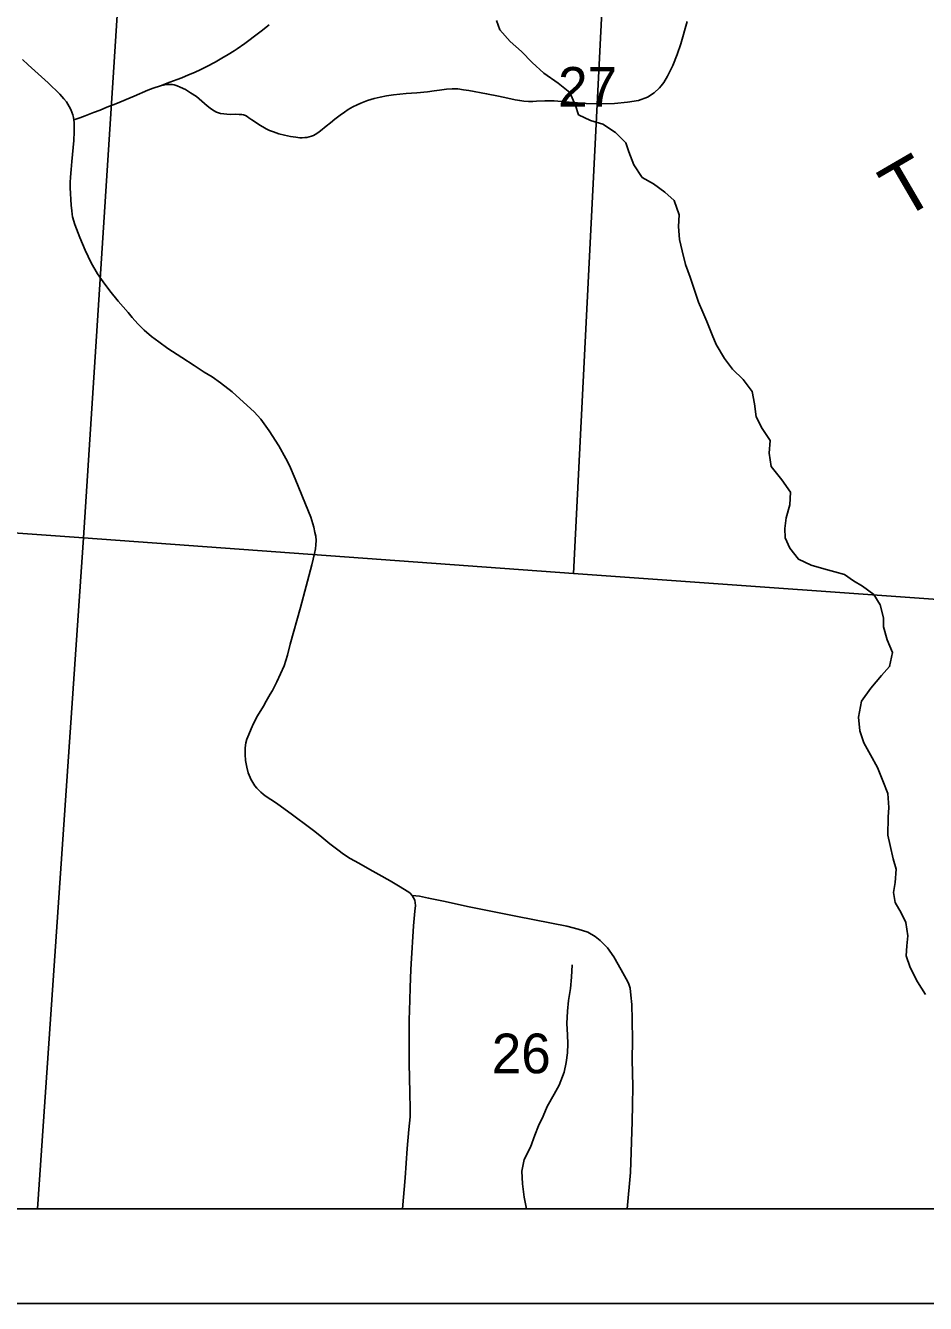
# Model space of a CAD drawing. Extents: x 0 to 34, y 0 to 22.
# Drawn here: x 4.184 to 5.134, y 14 to 15.349 of the extents above; entities that cross this region are included whole.
import ezdxf

# ---------------------------------------------------------------- set-up
doc = ezdxf.new("R2010")
doc.units = 0
for name, color, linetype in [('GM_X_Corporation', 7, 'Continuous'), ('GM_X_Minor_River', 7, 'Continuous'), ('GM_X_Section_Text', 7, 'Continuous'), ('GM_X_Township_Road', 7, 'Continuous'), ('GM_X_Township_Road_Text', 7, 'Continuous'), ('SH_Data', 7, 'Continuous')]:
    doc.layers.add(name, color=color, linetype=linetype)

msp = doc.modelspace()

# ---------------------------------------------------------------- linework, layer by layer
at = {"layer": 'GM_X_Corporation'}
for points in [[(3.3089, 15.8803), (3.31, 15.8916), (4.31, 15.819), (4.245, 14.8084), (3.2437, 14.8797)], [(4.31, 15.819), (4.8134, 15.7898), (4.7622, 14.7706), (4.245, 14.8084)], [(5.3151, 15.7607), (5.2401, 14.7366), (4.7622, 14.7706), (4.8134, 15.7898)], [(3.1916, 14.1), (4.1967, 14.1), (4.245, 14.8084), (3.2437, 14.8797)], [(4.1967, 14.1), (5.1981, 14.1), (5.2017, 14.1562), (5.23, 14.5792), (5.2401, 14.7366), (4.7622, 14.7706), (4.245, 14.8084)]]:
    msp.add_lwpolyline(points, close=True, dxfattribs=at)
at = {"layer": 'GM_X_Minor_River'}
for p, q in [((4.76, 14.3446), (4.7607, 14.3575)), ((4.759, 14.3324), (4.76, 14.3446)), ((4.7568, 14.3199), (4.759, 14.3324)), ((4.7558, 14.3085), (4.7568, 14.3199)), ((4.7551, 14.2956), (4.7558, 14.3085)), ((4.756, 14.2835), (4.7551, 14.2956)), ((4.7558, 14.2646), (4.7561, 14.274)), ((4.7561, 14.274), (4.756, 14.2835)), ((4.7544, 14.2543), (4.7558, 14.2646)), ((4.7522, 14.2441), (4.7544, 14.2543)), ((4.747, 14.2304), (4.7522, 14.2441)), ((4.7343, 14.2079), (4.7418, 14.2209)), ((4.7418, 14.2209), (4.747, 14.2304)), ((4.7303, 14.1976), (4.7343, 14.2079)), ((4.7254, 14.1874), (4.7303, 14.1976)), ((4.7214, 14.1775), (4.7254, 14.1874)), ((4.7169, 14.1649), (4.7214, 14.1775)), ((4.7077, 14.1398), (4.7102, 14.152)), ((4.7102, 14.152), (4.7169, 14.1649)), ((4.7082, 14.1262), (4.7077, 14.1398)), ((4.7102, 14.1122), (4.7082, 14.1262)), ((4.7122, 14.1016), (4.7102, 14.1122)), ((4.7122, 14.1), (4.7122, 14.1016))]:
    msp.add_line(p, q, dxfattribs=at)
for points in [[(5.0662, 14.6357), (5.0759, 14.6495), (5.0872, 14.6628), (5.0958, 14.6724), (5.0987, 14.6872), (5.0933, 14.7004), (5.0894, 14.7144), (5.0893, 14.7239), (5.0858, 14.7375), (5.0792, 14.7484), (5.067, 14.7574), (5.0575, 14.763), (5.048, 14.7697), (5.0378, 14.7723), (5.0264, 14.7756), (5.0128, 14.7793), (4.9995, 14.7856), (4.9903, 14.7972), (4.9856, 14.8082), (4.9852, 14.818), (4.9866, 14.8294), (4.9906, 14.8431), (4.9913, 14.8564), (4.9821, 14.8695), (4.9706, 14.8835), (4.9686, 14.8975), (4.9696, 14.9111), (4.9612, 14.9235), (4.955, 14.936), (4.953, 14.9496), (4.9506, 14.9629), (4.9411, 14.9753), (4.93, 14.9862), (4.9216, 14.9975), (4.9127, 15.0125), (4.9085, 15.0227), (4.9027, 15.0367), (4.8988, 15.0465), (4.8942, 15.0571), (4.8891, 15.0718), (4.8852, 15.0835), (4.8802, 15.0967), (4.8767, 15.1111), (4.8739, 15.1232), (4.8731, 15.1369), (4.8737, 15.1494), (4.8683, 15.1645), (4.8587, 15.1731), (4.8466, 15.1821), (4.8348, 15.1888), (4.8259, 15.202), (4.8205, 15.2156), (4.8174, 15.2254), (4.8064, 15.2363), (4.793, 15.2449), (4.7801, 15.2489), (4.7676, 15.2549), (4.7641, 15.2647), (4.7583, 15.2783), (4.7461, 15.2884), (4.7309, 15.2989), (4.7187, 15.3101), (4.7072, 15.3218), (4.6954, 15.3323), (4.6843, 15.3447), (4.6808, 15.3545)], [(5.1336, 14.326), (5.1252, 14.3395), (5.1175, 14.3546), (5.1132, 14.3671), (5.1139, 14.3777), (5.1149, 14.388), (5.1129, 14.4023), (5.1079, 14.4122), (5.1017, 14.4231), (5.0998, 14.4337), (5.1016, 14.4443), (5.1026, 14.4583), (5.0994, 14.4693), (5.0963, 14.4833), (5.0939, 14.4943), (5.0941, 14.5132), (5.0948, 14.5234), (5.0939, 14.5382), (5.0885, 14.5518), (5.0831, 14.5658), (5.0754, 14.579), (5.0685, 14.5918), (5.0642, 14.6046), (5.063, 14.619), (5.0662, 14.6357)]]:
    msp.add_lwpolyline(points, dxfattribs=at)
at = {"layer": 'GM_X_Township_Road'}
for points in [[(4.8545, 15.2853), (4.8576, 15.2891), (4.8615, 15.2956), (4.8671, 15.3068), (4.8716, 15.3184), (4.8755, 15.3298), (4.8821, 15.3532)], [(4.3265, 15.2856), (4.3363, 15.2892), (4.3438, 15.2921), (4.3487, 15.294), (4.3526, 15.2956), (4.3578, 15.2977), (4.3621, 15.2996), (4.369, 15.3028), (4.3753, 15.3059), (4.384, 15.3105), (4.3911, 15.3145), (4.3977, 15.3185), (4.404, 15.3225), (4.4072, 15.3246), (4.4152, 15.3301), (4.4195, 15.3332), (4.4255, 15.3377), (4.4324, 15.343), (4.441, 15.35)], [(4.5818, 14.1), (4.5845, 14.1325), (4.5865, 14.1635), (4.5885, 14.1836), (4.5897, 14.197), (4.5899, 14.2054), (4.5895, 14.2223), (4.5888, 14.2535), (4.5886, 14.281), (4.5887, 14.2991), (4.5893, 14.3201), (4.5897, 14.3335), (4.5906, 14.3526), (4.5909, 14.3585), (4.5934, 14.3987), (4.5949, 14.4141), (4.5954, 14.4201), (4.5947, 14.4257), (4.5919, 14.4306), (4.5893, 14.4335), (4.5866, 14.4353), (4.5792, 14.4398), (4.5775, 14.4408), (4.5687, 14.446), (4.5567, 14.4527), (4.5504, 14.4562), (4.5422, 14.4608), (4.5355, 14.4649), (4.5264, 14.4699), (4.5194, 14.4744), (4.5133, 14.4788), (4.5052, 14.4853), (4.4966, 14.4921), (4.4891, 14.4984), (4.4836, 14.5025), (4.4655, 14.5157), (4.4488, 14.528), (4.4369, 14.5358), (4.4346, 14.5376), (4.4323, 14.5396), (4.428, 14.5441), (4.4259, 14.5466), (4.4226, 14.5517), (4.4216, 14.5536), (4.4211, 14.5553), (4.4189, 14.5603), (4.4173, 14.566), (4.4161, 14.5731), (4.4156, 14.5794), (4.4156, 14.5866), (4.4164, 14.5918), (4.4174, 14.5958), (4.4195, 14.6008), (4.4219, 14.6066), (4.4245, 14.6121), (4.4288, 14.6203), (4.435, 14.6307), (4.4377, 14.6357), (4.4422, 14.6433), (4.4444, 14.6472), (4.4491, 14.6561), (4.4567, 14.6731), (4.4603, 14.6845), (4.4631, 14.6959), (4.474, 14.7348), (4.486, 14.7798), (4.4889, 14.7917), (4.4898, 14.7966), (4.4903, 14.8007), (4.4906, 14.8055), (4.4901, 14.8099), (4.4892, 14.814), (4.4882, 14.8195), (4.485, 14.8301), (4.4825, 14.8361), (4.4683, 14.8707), (4.4623, 14.8846), (4.4585, 14.8921), (4.4513, 14.9055), (4.4409, 14.9212), (4.4321, 14.9336), (4.4251, 14.9413), (4.414, 14.9515), (4.4018, 14.9624), (4.3898, 14.9719), (4.3807, 14.9781), (4.3725, 14.9833), (4.3619, 14.9901), (4.3488, 14.9985), (4.3342, 15.008), (4.3245, 15.0151), (4.3169, 15.0207), (4.3091, 15.0274), (4.3024, 15.0343), (4.2965, 15.0407), (4.2922, 15.046), (4.2816, 15.0581), (4.2728, 15.069), (4.2659, 15.0785), (4.2599, 15.087), (4.2533, 15.0985), (4.247, 15.1119), (4.2413, 15.1254), (4.2361, 15.1389), (4.2336, 15.1473), (4.233, 15.1501), (4.2327, 15.1533), (4.2322, 15.1593), (4.2311, 15.1778), (4.2309, 15.1833), (4.2313, 15.1891), (4.232, 15.1971), (4.2329, 15.2055), (4.2349, 15.2277), (4.2354, 15.237), (4.2352, 15.2463), (4.2348, 15.2494), (4.2345, 15.2519), (4.2338, 15.2549), (4.2328, 15.2578), (4.2317, 15.2606), (4.23, 15.2636), (4.227, 15.2684), (4.2245, 15.2716), (4.22, 15.2766), (4.2077, 15.2887), (4.1867, 15.3075), (4.1806, 15.3133)], [(4.2348, 15.2494), (4.2412, 15.2518), (4.2467, 15.2539), (4.2558, 15.2573), (4.2626, 15.2599), (4.2698, 15.2628), (4.2791, 15.2665), (4.2986, 15.2746), (4.3129, 15.2808), (4.3185, 15.283), (4.3265, 15.2856), (4.3325, 15.2867), (4.3347, 15.2869), (4.3367, 15.2869), (4.3389, 15.2868), (4.3408, 15.2864), (4.3439, 15.2855), (4.3472, 15.2841), (4.3526, 15.2814), (4.3581, 15.2782), (4.3642, 15.2741), (4.3701, 15.2694), (4.3756, 15.2644), (4.3787, 15.2619), (4.3822, 15.2595), (4.3854, 15.2575), (4.3896, 15.2563), (4.3999, 15.2552), (4.4054, 15.2554), (4.4094, 15.2553), (4.4121, 15.2552), (4.4141, 15.2548), (4.4162, 15.254), (4.4178, 15.253), (4.4196, 15.2518), (4.4227, 15.2495), (4.4275, 15.2464), (4.4313, 15.244), (4.4345, 15.242), (4.4377, 15.2402), (4.4414, 15.2384), (4.4455, 15.2367), (4.4512, 15.2349), (4.4573, 15.2333), (4.4636, 15.232), (4.4693, 15.2311), (4.4734, 15.2307), (4.476, 15.2306), (4.4785, 15.2308), (4.4806, 15.231), (4.4833, 15.2316), (4.4858, 15.2323), (4.4877, 15.2331), (4.4897, 15.2341), (4.4924, 15.2358), (4.4952, 15.2378), (4.5012, 15.2427), (4.5057, 15.2465), (4.5102, 15.2503), (4.5158, 15.2546), (4.5204, 15.2578), (4.5244, 15.2604), (4.5294, 15.2633), (4.5338, 15.2655), (4.5377, 15.2671), (4.5449, 15.2698), (4.5517, 15.2719), (4.5582, 15.2734), (4.5647, 15.2747), (4.5723, 15.2759), (4.5855, 15.2772), (4.5967, 15.278), (4.6082, 15.279), (4.6152, 15.2801), (4.6208, 15.281), (4.628, 15.282), (4.6341, 15.2823), (4.6401, 15.2821), (4.6461, 15.2813), (4.6517, 15.2804), (4.6705, 15.277), (4.6831, 15.2745), (4.693, 15.2723), (4.7006, 15.2707), (4.7055, 15.2698), (4.7097, 15.2693), (4.7146, 15.2689), (4.7192, 15.2689), (4.7232, 15.2691), (4.7319, 15.2695), (4.7417, 15.2695), (4.7575, 15.2681), (4.7756, 15.2667), (4.7906, 15.2663), (4.8054, 15.2667), (4.8192, 15.2681), (4.8306, 15.27), (4.8403, 15.2733), (4.8474, 15.2781), (4.853, 15.2833), (4.8545, 15.2853)], [(4.8187, 14.1), (4.8224, 14.1384), (4.8242, 14.192), (4.8244, 14.2092), (4.8248, 14.229), (4.8241, 14.2577), (4.8244, 14.2775), (4.8242, 14.2993), (4.8236, 14.3156), (4.8228, 14.3254), (4.822, 14.3327), (4.8202, 14.338), (4.8179, 14.3426), (4.8142, 14.3489), (4.8092, 14.3577), (4.8047, 14.366), (4.7981, 14.3753), (4.7903, 14.3833), (4.7852, 14.3875), (4.7773, 14.3919), (4.7671, 14.3952), (4.7553, 14.3982), (4.7032, 14.4085), (4.6608, 14.4171), (4.6503, 14.4192), (4.6267, 14.4243), (4.6093, 14.428), (4.5996, 14.4298), (4.5919, 14.4306)]]:
    msp.add_lwpolyline(points, dxfattribs=at)
at = {"layer": 'SH_Data'}
for p, q in [((2.1, 14.1), (8.9, 14.1)), ((2, 14), (9, 14))]:
    msp.add_line(p, q, dxfattribs=at)

# ---------------------------------------------------------------- texts
at = {"layer": 'GM_X_Section_Text'}
for s, p in [('27', (4.7459, 15.2634)), ('26', (4.6759, 14.243))]:
    msp.add_text(s, height=0.04186, rotation=0, dxfattribs=at).set_placement(p)
at = {"layer": 'GM_X_Township_Road_Text'}
msp.add_text('T', height=0.0568, rotation=30.2398, dxfattribs=at).set_placement((5.1084, 15.1435))

doc.saveas('drawing.dxf')
